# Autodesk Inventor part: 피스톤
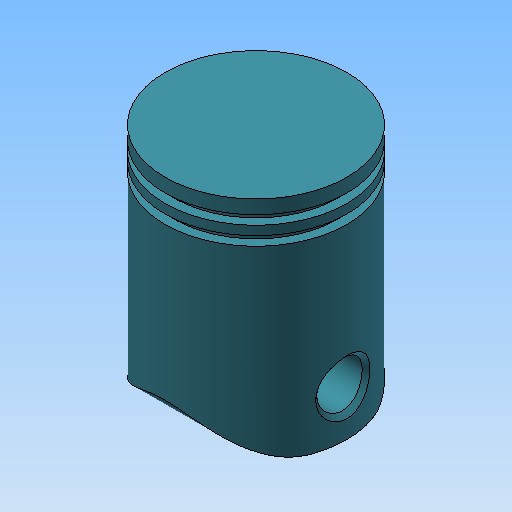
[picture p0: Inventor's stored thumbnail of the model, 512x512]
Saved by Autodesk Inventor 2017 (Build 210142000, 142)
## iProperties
Created: 2017-05
Part Number: 피스톤
Material: 알루미늄 6061
Document SubType Name: Modeling
Designer: mduedu
Density: 2.71 g/cm^3
Mass: 87.6985 g
Surface Area: 150.47 cm^2
Volume: 32.3611 cm^3
Appearance: 커뎃 파란색
Author: mduedu
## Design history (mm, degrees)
sketch "스케치1"
  geometry: L1 (0, 0)-(20, 0); L2 (20, -50)-(15, -50); L3 (15, -50)-(15, -5); L4 (15, -5)-(0, -5); L5 (0, -5)-(0, 0); L6 (20, -3)-(18, -3); L7 (18, -3)-(18, -5); L8 (18, -5)-(20, -5); L9 (20, -7)-(18, -7); L10 (18, -7)-(18, -9); L11 (18, -9)-(20, -9); L12 (20, 0)-(20, -3); L13 (20, -5)-(20, -7); L14 (20, -9)-(20, -50); L15 (0, -60)-(0, 10) reference
  constraints: 28 end point, 10 parallel, 5 perpendicular, 4 collinear, 3 horizontal
  dimensions: "d0" = 20 distance of L1.start L1.end; "d1" = 2 distance of L6.start L6.end; "d2" = 2 distance of L6.end L7.end; "d3" = 2 distance of L8.end L9.start; "d4" = 3 distance of L1.end L6.start; "d5" = 5 distance of L2.start L2.end; "d6" = 50 distance between parallel lines of L1 L2; "d7" = 5 distance of L4.end L1.start
revolve "회전1" sketch "스케치1" stored, may be unused: angle "d8" = 90 deg
fillet "모깎기1" dims "d9" = 1
sketch "스케치2"
  geometry: L1 (-50, 15)-(-50, -15) reference; C1 r 10 at (-40, 0); 1 further point
  constraints: 1 centre point, 1 horizontal alignment
  dimensions: "d10" = 20 diameter of C1; "d11" = 10 distance from line of C1.centre L1
extrude "돌출1" join sketch "스케치2" stored distance "d12" = 10; taper "d13" = 0 deg
sketch "스케치3"
  geometry: L1 (0, -20)-(-3, -20) reference; L2 (-3, -20)-(-3, -18) reference; L3 (-3, -18)-(-5, -18) reference; L4 (-5, -18)-(-5, -20) reference; L5 (-5, -20)-(-7, -20) reference; L6 (-7, -20)-(-7, -18) reference; L7 (-7, -18)-(-9, -18) reference; L8 (-9, -18)-(-9, -20) reference; L9 (-9, -20)-(-50, -20) reference; L10 (-50, -20)-(-50, -15) reference; L11 (-50, -15)-(-6, -15) reference; L12 (-5, -14)-(-5, 14) reference; L13 (-6, 15)-(-50, 15) reference; L14 (-50, 15)-(-50, 20) reference; L15 (-50, 20)-(-9, 20) reference; L16 (-9, 20)-(-9, 18) reference; L17 (-9, 18)-(-7, 18) reference; L18 (-7, 18)-(-7, 20) reference; L19 (-7, 20)-(-5, 20) reference; L20 (-5, 20)-(-5, 18) reference; L21 (-5, 18)-(-3, 18) reference; L22 (-3, 18)-(-3, 20) reference; L23 (-3, 20)-(0, 20) reference; L24 (0, 20)-(0, -20) reference; C1 r 10 at (-40, 0) reference; C2 r 5 at (-40, 0); A1 r 1 centre (-6, -14) between (-6, -15) and (-5, -14) reference; A2 r 1 centre (-6, 14) between (-5, 14) and (-6, 15) reference; 1 further point
  constraints: 1 centre point, 1 coincident
  dimensions: "d15" = 10 diameter of C2
extrude "돌출2" cut sketch "스케치3" stored distance "d16" = 10; taper "d17" = 0 deg
sketch "스케치4"
  geometry: L1 (15, -50)-(-15, -50) reference; L2 (-15, -50)-(-20, -50) reference; L3 (-20, -50)-(-20, -45) reference; L4 (20, -45)-(20, -50) reference; L5 (20, -50)-(15, -50) reference; L6 (-15, -30)-(15, -30) reference; L7 (15, -30)-(15, -6) reference; L8 (14, -5)-(-14, -5) reference; L9 (-15, -6)-(-15, -30) reference; L10 (-20, -3)-(-20, 0) reference; L11 (-20, 0)-(20, 0) reference; L12 (20, 0)-(20, -3) reference; L13 (20, -3)-(18, -3) reference; L14 (18, -3)-(18, -5) reference; L15 (18, -5)-(20, -5) reference; L16 (20, -5)-(20, -7) reference; L17 (20, -7)-(18, -7) reference; L18 (18, -7)-(18, -9) reference; L19 (18, -9)-(20, -9) reference; L20 (-20, -9)-(-18, -9) reference; L21 (-18, -9)-(-18, -7) reference; L22 (-18, -7)-(-20, -7) reference; L23 (-20, -7)-(-20, -5) reference; L24 (-20, -5)-(-18, -5) reference; L25 (-18, -5)-(-18, -3) reference; L26 (-18, -3)-(-20, -3) reference; L27 (0, 0)-(0, -50); L28 (-5.698, -50)-(-5, -30); L29 (5.698, -50)-(5, -30); L30 (-5, -30)-(5, -30); L31 (-5.698, -50)-(5.698, -50); L32 (-20, -45)-(20, -45) reference; L33 (20, -9)-(20, -35) reference; L34 (20, -35)-(-20, -35) reference; L35 (-20, -35)-(-20, -9) reference; A1 r 1 centre (14, -6) between (15, -6) and (14, -5) reference; A2 r 1 centre (-14, -6) between (-14, -5) and (-15, -6) reference
  constraints: 10 end point, 2 point on line, 2 symmetric about line, 1 midpoint, 1 parallel, 1 perpendicular
  dimensions: "d18" = 2 deg angle of L27 L28; "d19" = 5 distance from line of L27 L28.end
extrude "돌출3" cut sketch "스케치4" stored distance "d20" = 20; taper "d21" = 0 deg
chamfer "모따기1" distance "d22" = 1; stored, may be unused: second distance "d23" = 2, angle "d24" = 45 deg
sketch "스케치5"
  geometry: L1 (-50, 0)-(-50, -15) reference; L2 (-50, 15)-(-50, 0) reference; L3 (-9, 20)-(-50, 20) reference; L4 (-50, 20)-(-50, -20) reference; L5 (-9, -20)-(-50, -20) reference; L6 (-42.483, -20)-(-50, -20); L7 (-50, -20)-(-50, -7); L8 (-42.483, 20)-(-50, 20); L9 (-50, 20)-(-50, 7); A1 r 15 centre (-35, 7) between (-42.483, 20) and (-50, 7); A2 r 15 centre (-35, -7) between (-42.483, -20) and (-50, -7); 1 further point
  constraints: 8 end point, 4 point on circle, 4 point on line, 2 centre point, 2 tangent, 1 collinear, 1 equal radius, 1 perpendicular
  dimensions: "d25" = 30 diameter of A1; "d26" = 7 vertical distance of A2.centre point (0, 0); "d27" = 7 vertical distance of point (0, 0) A1.centre (= d26)
extrude "돌출4" cut sketch "스케치5" stored distance "d28" = 20; taper "d29" = 0 deg
node "솔리드1"
node "절단 모서리 투영1"
node "절단 모서리 투영2"
